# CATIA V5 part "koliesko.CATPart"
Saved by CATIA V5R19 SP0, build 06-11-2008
Part number: koliesko
Bounding box of the stored display mesh (mm): x -3.996 to 3.996, y -7 to 7, z -3.999 to 3.999
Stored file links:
  C:\Users\Jozef Drozd\Desktop\zostava\koliesko.CATPart
  C:\Program Files (x86)\Dassault Systemes\B19\intel_a\startup\materials\Catalog.CATMaterial
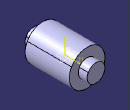
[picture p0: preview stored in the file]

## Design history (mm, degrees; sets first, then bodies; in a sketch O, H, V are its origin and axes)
Body1 (main body)
  Sketch1 on xy-plane, origin (0, 0, 0), H (1, 0, 0), V (0, 1, 0)
    point P1 (0, 5)
    line L1 (2, 5) -> (4, 5)
    line L2 (4, 5) -> (4, -5)
    line L3 (4, -5) -> (2, -5)
    line L4 (0, -5) -> (0, 5)
    point P5 (2.5, 5)
    point P6 (0, 7)
    line L5 (0, 7) -> (2, 7)
    line L6 (2, 7) -> (2, 5)
    line L7 (0, 5) -> (0, 7)
    line L8 (2, -5) -> (2, -7)
    line L9 (2, -7) -> (0, -7)
    line L10 (0, -7) -> (0, -5)
    point P11 (2, -7)
    axis line L11 (0, -9) -> (0, -12)
    point P13 (0, -9)
    distance L2 L4 = 4
    coincidence: P1 V, P6 V, P11 L6, L1 P5, P13 V
    horizontal: L1 H, L3 H, L5 H, L9 H
    vertical: L2 V, L4 V, L6 V, L7 V, L8 V, L10 V, L11 V
  Shaft1: profile Sketch1, axis Sketch1.L11, angle 360
  Sketch2 on yz-plane, origin (0, 0, 0), H (0, 1, 0), V (0, 0, 1)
